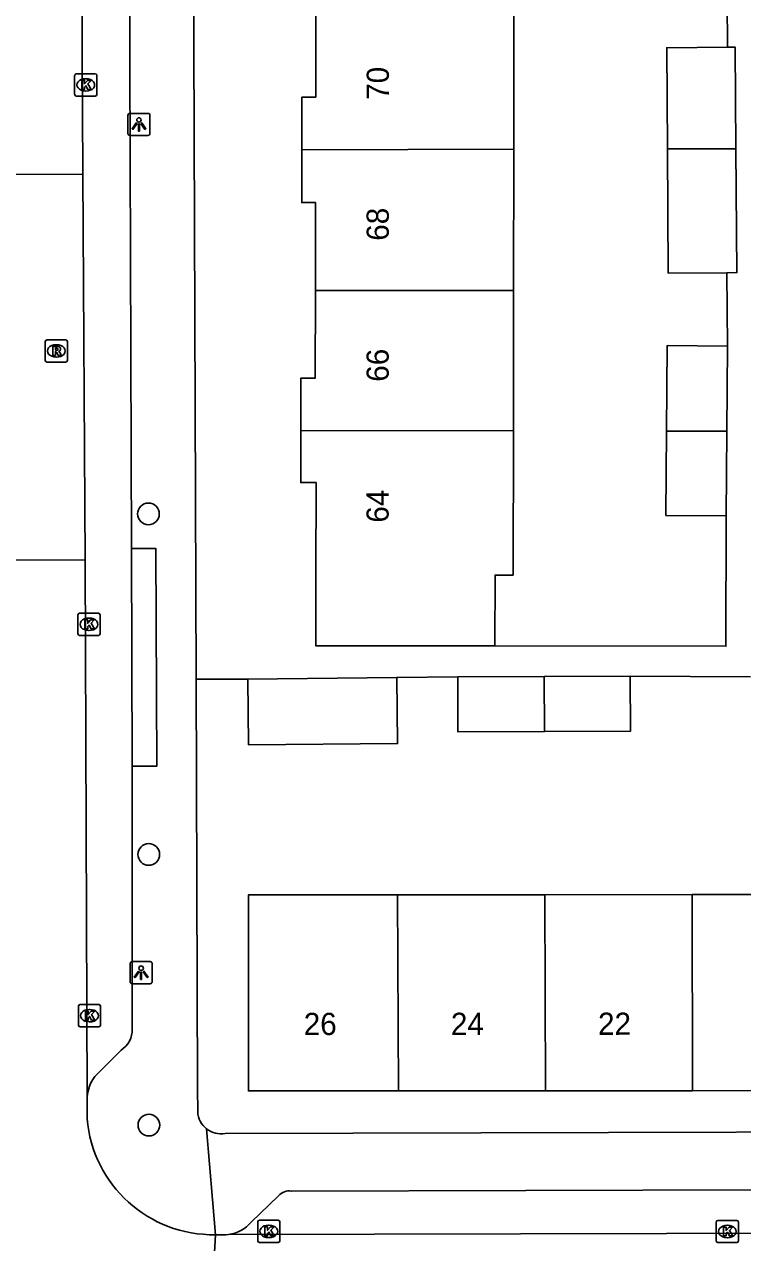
# Model space of a CAD drawing. Extents: x 160732 to 162105, y 387428 to 388479.
# Drawn here: x 161158.5 to 161190.9, y 388093.4 to 388148.3 of the extents above; entities that cross this region are included whole.
import ezdxf

# ---------------------------------------------------------------- set-up
doc = ezdxf.new("R2010")
doc.units = 0
for name, color, linetype in [('IMGEO_Boom', 7, 'Continuous'), ('IMGEO_Kolk', 7, 'Continuous'), ('IMGEO_Lichtpunt', 7, 'Continuous'), ('IMGEO_Pand', 7, 'Continuous'), ('IMGEO_Pand_nummerreeks', 7, 'Continuous'), ('IMGEO_Rijbaan_lokaal_open', 7, 'Continuous'), ('IMGEO_Rioolput', 7, 'Continuous'), ('IMGEO_Voetpad_open', 7, 'Continuous')]:
    doc.layers.add(name, color=color, linetype=linetype)

msp = doc.modelspace()

# ---------------------------------------------------------------- linework, layer by layer
at = {"layer": 'IMGEO_Boom'}
for centre in [(161164.081, 388126.239), (161164.092, 388110.889), (161164.1, 388098.689)]:
    msp.add_circle(centre, 0.489, dxfattribs=at)
at = {"layer": 'IMGEO_Kolk'}
for p, q in [((161160.752, 388145.149), (161160.752, 388146.001)), ((161160.827, 388146.075), (161161.679, 388146.075)), ((161161.24, 388145.855), (161161.265, 388145.855)), ((161161.753, 388146.001), (161161.753, 388145.149)), ((161161.263, 388145.295), (161161.238, 388145.295)), ((161161.679, 388145.075), (161160.827, 388145.075)), ((161160.897, 388120.836), (161160.897, 388121.688)), ((161160.972, 388121.762), (161161.824, 388121.762)), ((161161.385, 388121.542), (161161.41, 388121.542)), ((161161.898, 388121.688), (161161.898, 388120.836)), ((161161.408, 388120.982), (161161.383, 388120.982)), ((161161.824, 388120.762), (161160.972, 388120.762)), ((161160.92, 388103.195), (161160.92, 388104.047)), ((161160.995, 388104.121), (161161.847, 388104.121)), ((161161.921, 388104.047), (161161.921, 388103.195)), ((161161.408, 388103.901), (161161.433, 388103.901)), ((161161.847, 388103.121), (161160.995, 388103.121)), ((161161.431, 388103.341), (161161.406, 388103.341)), ((161169.007, 388093.473), (161169.007, 388094.325)), ((161169.082, 388094.399), (161169.934, 388094.399)), ((161169.495, 388094.179), (161169.52, 388094.179)), ((161170.008, 388094.325), (161170.008, 388093.473)), ((161189.689, 388093.467), (161189.689, 388094.319)), ((161189.764, 388094.393), (161190.616, 388094.393)), ((161190.177, 388094.173), (161190.202, 388094.173)), ((161190.69, 388094.319), (161190.69, 388093.467)), ((161169.518, 388093.619), (161169.493, 388093.619)), ((161190.2, 388093.613), (161190.175, 388093.613)), ((161169.934, 388093.399), (161169.082, 388093.399)), ((161190.616, 388093.393), (161189.764, 388093.393))]:
    msp.add_line(p, q, dxfattribs=at)
for points in [[(161160.752, 388145.149), (161160.752, 388146.001)], [(161160.827, 388146.075), (161161.679, 388146.075)], [(161161.073, 388145.775), (161161.196, 388145.775), (161161.196, 388145.624), (161161.326, 388145.775), (161161.49, 388145.775), (161161.344, 388145.624), (161161.497, 388145.375), (161161.345, 388145.375), (161161.26, 388145.539), (161161.196, 388145.472), (161161.196, 388145.375), (161161.073, 388145.375), (161161.073, 388145.775)], [(161161.753, 388146.001), (161161.753, 388145.149)], [(161161.679, 388145.075), (161160.827, 388145.075)], [(161160.897, 388120.836), (161160.897, 388121.688)], [(161160.972, 388121.762), (161161.824, 388121.762)], [(161161.898, 388121.688), (161161.898, 388120.836)], [(161161.218, 388121.462), (161161.341, 388121.462), (161161.341, 388121.311), (161161.471, 388121.462), (161161.635, 388121.462), (161161.489, 388121.311), (161161.642, 388121.062), (161161.49, 388121.062), (161161.405, 388121.226), (161161.341, 388121.159), (161161.341, 388121.062), (161161.218, 388121.062), (161161.218, 388121.462)], [(161161.824, 388120.762), (161160.972, 388120.762)], [(161160.92, 388103.195), (161160.92, 388104.047)], [(161160.995, 388104.121), (161161.847, 388104.121)], [(161161.921, 388104.047), (161161.921, 388103.195)], [(161161.241, 388103.821), (161161.364, 388103.821), (161161.364, 388103.67), (161161.494, 388103.821), (161161.658, 388103.821), (161161.512, 388103.67), (161161.665, 388103.421), (161161.513, 388103.421), (161161.428, 388103.585), (161161.364, 388103.518), (161161.364, 388103.421), (161161.241, 388103.421), (161161.241, 388103.821)], [(161161.847, 388103.121), (161160.995, 388103.121)], [(161169.007, 388093.473), (161169.007, 388094.325)], [(161169.082, 388094.399), (161169.934, 388094.399)], [(161169.328, 388094.099), (161169.451, 388094.099), (161169.451, 388093.948), (161169.581, 388094.099), (161169.745, 388094.099), (161169.599, 388093.948), (161169.752, 388093.699), (161169.6, 388093.699), (161169.515, 388093.863), (161169.451, 388093.796), (161169.451, 388093.699), (161169.328, 388093.699), (161169.328, 388094.099)], [(161170.008, 388094.325), (161170.008, 388093.473)], [(161189.689, 388093.467), (161189.689, 388094.319)], [(161189.764, 388094.393), (161190.616, 388094.393)], [(161190.01, 388094.093), (161190.133, 388094.093), (161190.133, 388093.942), (161190.263, 388094.093), (161190.427, 388094.093), (161190.281, 388093.942), (161190.434, 388093.693), (161190.282, 388093.693), (161190.197, 388093.857), (161190.133, 388093.79), (161190.133, 388093.693), (161190.01, 388093.693), (161190.01, 388094.093)], [(161190.69, 388094.319), (161190.69, 388093.467)], [(161169.934, 388093.399), (161169.082, 388093.399)], [(161190.616, 388093.393), (161189.764, 388093.393)]]:
    msp.add_lwpolyline(points, dxfattribs=at)
for centre, start, end in [((161160.829, 388145.999), 91.552, 178.448), ((161160.829, 388145.999), 91.552, 178.448), ((161161.677, 388145.999), 1.552, 88.448), ((161161.677, 388145.999), 1.552, 88.448), ((161160.829, 388145.151), 181.552, 268.448), ((161160.829, 388145.151), 181.552, 268.448), ((161161.677, 388145.151), 271.552, 358.448), ((161161.677, 388145.151), 271.552, 358.448), ((161160.974, 388121.686), 91.552, 178.448), ((161160.974, 388121.686), 91.552, 178.448), ((161161.822, 388121.686), 1.552, 88.448), ((161161.822, 388121.686), 1.552, 88.448), ((161160.974, 388120.838), 181.552, 268.448), ((161160.974, 388120.838), 181.552, 268.448), ((161161.822, 388120.838), 271.552, 358.448), ((161161.822, 388120.838), 271.552, 358.448), ((161160.997, 388104.045), 91.552, 178.448), ((161160.997, 388104.045), 91.552, 178.448), ((161161.845, 388104.045), 1.552, 88.448), ((161161.845, 388104.045), 1.552, 88.448), ((161160.997, 388103.197), 181.552, 268.448), ((161160.997, 388103.197), 181.552, 268.448), ((161161.845, 388103.197), 271.552, 358.448), ((161161.845, 388103.197), 271.552, 358.448), ((161169.084, 388094.323), 91.552, 178.448), ((161169.084, 388094.323), 91.552, 178.448), ((161169.932, 388094.323), 1.552, 88.448), ((161169.932, 388094.323), 1.552, 88.448), ((161189.766, 388094.317), 91.552, 178.448), ((161189.766, 388094.317), 91.552, 178.448), ((161190.614, 388094.317), 1.552, 88.448), ((161190.614, 388094.317), 1.552, 88.448), ((161169.084, 388093.475), 181.552, 268.448), ((161169.084, 388093.475), 181.552, 268.448), ((161169.932, 388093.475), 271.552, 358.448), ((161169.932, 388093.475), 271.552, 358.448), ((161189.766, 388093.469), 181.552, 268.448), ((161189.766, 388093.469), 181.552, 268.448), ((161190.614, 388093.469), 271.552, 358.448), ((161190.614, 388093.469), 271.552, 358.448)]:
    msp.add_arc(centre, 0.0765, start, end, dxfattribs=at)
for centre, major_axis, ratio, start_param, end_param in [((161161.239, 388145.575), (-0.387, 0.002), 0.722429, 4.712389, 7.853982), ((161161.264, 388145.575), (-0.39, 0.002), 0.717154, 1.570796, 4.712389), ((161161.384, 388121.262), (-0.387, 0.002), 0.722429, 4.712389, 7.853982), ((161161.409, 388121.262), (-0.39, 0.002), 0.717154, 1.570796, 4.712389), ((161161.407, 388103.621), (-0.387, 0.002), 0.722429, 4.712389, 7.853982), ((161161.432, 388103.621), (-0.39, 0.002), 0.717154, 1.570796, 4.712389), ((161169.494, 388093.899), (-0.387, 0.002), 0.722429, 4.712389, 7.853982), ((161169.519, 388093.899), (-0.39, 0.002), 0.717154, 1.570796, 4.712389), ((161190.176, 388093.893), (-0.387, 0.002), 0.722429, 4.712389, 7.853982), ((161190.201, 388093.893), (-0.39, 0.002), 0.717154, 1.570796, 4.712389)]:
    msp.add_ellipse(centre, major_axis=major_axis, ratio=ratio, start_param=start_param, end_param=end_param, dxfattribs=at)
at = {"layer": 'IMGEO_Lichtpunt'}
for p, q in [((161163.152, 388144.198), (161163.152, 388143.391)), ((161163.152, 388144.198), (161163.152, 388143.391)), ((161164.054, 388144.293), (161163.246, 388144.293)), ((161164.054, 388144.293), (161163.246, 388144.293)), ((161164.148, 388143.391), (161164.148, 388144.198)), ((161164.148, 388143.391), (161164.148, 388144.198)), ((161163.246, 388143.297), (161164.054, 388143.297)), ((161163.246, 388143.297), (161164.054, 388143.297)), ((161163.251, 388105.963), (161163.251, 388105.156)), ((161163.251, 388105.963), (161163.251, 388105.156)), ((161164.153, 388106.058), (161163.345, 388106.058)), ((161164.153, 388106.058), (161163.345, 388106.058)), ((161164.247, 388105.156), (161164.247, 388105.963)), ((161164.247, 388105.156), (161164.247, 388105.963)), ((161163.345, 388105.062), (161164.153, 388105.062)), ((161163.345, 388105.062), (161164.153, 388105.062))]:
    msp.add_line(p, q, dxfattribs=at)
for points in [[(161163.526, 388143.862), (161163.565, 388143.834), (161163.377, 388143.572), (161163.339, 388143.599), (161163.526, 388143.862)], [(161163.628, 388143.814), (161163.675, 388143.814), (161163.675, 388143.492), (161163.628, 388143.492), (161163.628, 388143.814)], [(161163.738, 388143.834), (161163.776, 388143.861), (161163.963, 388143.599), (161163.924, 388143.571), (161163.738, 388143.834)], [(161163.625, 388105.627), (161163.664, 388105.599), (161163.476, 388105.337), (161163.438, 388105.364), (161163.625, 388105.627)], [(161163.727, 388105.579), (161163.774, 388105.579), (161163.774, 388105.257), (161163.727, 388105.257), (161163.727, 388105.579)], [(161163.837, 388105.599), (161163.875, 388105.626), (161164.062, 388105.364), (161164.023, 388105.336), (161163.837, 388105.599)]]:
    msp.add_lwpolyline(points, dxfattribs=at)
for centre in [(161163.651, 388143.996), (161163.75, 388105.761)]:
    msp.add_circle(centre, 0.0994, dxfattribs=at)
for centre, start, end in [((161163.246, 388144.198), 90, 180), ((161163.246, 388144.198), 90, 180), ((161164.054, 388144.198), 0, 90), ((161164.054, 388144.198), 0, 90), ((161163.246, 388143.391), 180, 270), ((161163.246, 388143.391), 180, 270), ((161164.054, 388143.391), 270, 0), ((161164.054, 388143.391), 270, 360), ((161163.345, 388105.963), 90, 180), ((161163.345, 388105.963), 90, 180), ((161164.153, 388105.963), 0, 90), ((161164.153, 388105.963), 0, 90), ((161163.345, 388105.156), 180, 270), ((161163.345, 388105.156), 180, 270), ((161164.153, 388105.156), 270, 0), ((161164.153, 388105.156), 270, 360)]:
    msp.add_arc(centre, 0.0946, start, end, dxfattribs=at)
at = {"layer": 'IMGEO_Pand'}
for points in [[(161171, 388142.65), (161171.003, 388145.028), (161171.627, 388145.028), (161171.633, 388148.992)], [(161180.565, 388149.007), (161180.556, 388142.675)], [(161190.201, 388147.273), (161187.452, 388147.253), (161187.485, 388142.693)], [(161190.201, 388147.273), (161190.543, 388147.276), (161190.576, 388142.701)], [(161171, 388142.65), (161170.997, 388140.269), (161171.615, 388140.268), (161171.61, 388136.315)], [(161180.556, 388142.675), (161171, 388142.65)], [(161180.547, 388136.303), (161180.556, 388142.675)], [(161187.485, 388142.693), (161190.576, 388142.701)], [(161187.485, 388142.693), (161187.526, 388137.091), (161190.166, 388137.111)], [(161190.576, 388142.701), (161190.617, 388137.114), (161190.166, 388137.111)], [(161170.955, 388130.005), (161170.958, 388132.361), (161171.604, 388132.36), (161171.61, 388136.315)], [(161171.61, 388136.315), (161180.547, 388136.303)], [(161180.547, 388136.303), (161180.538, 388129.985)], [(161187.443, 388129.971), (161187.472, 388133.824), (161190.191, 388133.803)], [(161190.191, 388133.803), (161190.162, 388129.965)], [(161170.955, 388130.005), (161170.952, 388127.652), (161171.638, 388127.651), (161171.632, 388123.494), (161171.627, 388120.298), (161179.707, 388120.286)], [(161180.538, 388129.985), (161170.955, 388130.005)], [(161179.707, 388120.286), (161179.712, 388123.483), (161180.528, 388123.482), (161180.538, 388129.985)], [(161190.133, 388126.15), (161187.415, 388126.17), (161187.443, 388129.971)], [(161187.443, 388129.971), (161190.162, 388129.965)], [(161190.162, 388129.965), (161190.133, 388126.15)], [(161168.569, 388118.796), (161175.284, 388118.862)], [(161175.284, 388118.862), (161175.313, 388115.888), (161168.598, 388115.822), (161168.569, 388118.796)], [(161178.027, 388118.888), (161181.93, 388118.904)], [(161181.938, 388116.43), (161178.038, 388116.414), (161178.027, 388118.888)], [(161181.93, 388118.904), (161185.812, 388118.92)], [(161181.938, 388116.43), (161181.93, 388118.904)], [(161185.812, 388118.92), (161185.823, 388116.446), (161181.938, 388116.43)], [(161175.35, 388100.231), (161168.592, 388100.226), (161168.585, 388109.065), (161175.319, 388109.07)], [(161175.319, 388109.07), (161181.961, 388109.075)], [(161175.35, 388100.231), (161175.319, 388109.07)], [(161181.961, 388109.075), (161188.594, 388109.08)], [(161181.989, 388100.236), (161181.961, 388109.075)], [(161188.594, 388109.08), (161195.217, 388109.084)], [(161188.62, 388100.24), (161188.594, 388109.08)], [(161181.989, 388100.236), (161175.35, 388100.231)], [(161188.62, 388100.24), (161181.989, 388100.236)], [(161195.251, 388100.245), (161188.62, 388100.24)]]:
    msp.add_lwpolyline(points, dxfattribs=at)
at = {"layer": 'IMGEO_Rijbaan_lokaal_open'}
for points in [[(161161.118, 388141.556), (161160.945, 388175.907)], [(161156.023, 388141.534), (161161.118, 388141.556)], [(161161.231, 388124.147), (161161.118, 388141.556)], [(161161.231, 388124.147), (161156.115, 388124.167)], [(161161.317, 388099.948), (161161.231, 388124.147)], [(161161.317, 388099.948), (161161.311, 388098.979)], [(161166.812, 388088.76), (161167.102, 388093.748)], [(161167.689, 388093.754), (161167.577, 388093.743), (161167.102, 388093.748)], [(161246.71, 388093.94), (161167.689, 388093.754)]]:
    msp.add_lwpolyline(points, dxfattribs=at)
msp.add_arc((161167.006, 388099.462), 5.715, 184.8512, 270.9659, dxfattribs=at)
at = {"layer": 'IMGEO_Rioolput'}
for p, q in [((161159.424, 388133.158), (161159.424, 388134.01)), ((161159.499, 388134.084), (161160.351, 388134.084)), ((161159.912, 388133.864), (161159.937, 388133.864)), ((161160.425, 388134.01), (161160.425, 388133.158)), ((161160.351, 388133.084), (161159.499, 388133.084)), ((161159.935, 388133.304), (161159.91, 388133.304))]:
    msp.add_line(p, q, dxfattribs=at)
for points in [[(161159.424, 388133.158), (161159.424, 388134.01)], [(161159.499, 388134.084), (161160.351, 388134.084)], [(161160.013, 388133.782), (161159.761, 388133.784), (161159.761, 388133.384)], [(161159.939, 388133.703), (161159.885, 388133.703), (161159.885, 388133.622)], [(161159.885, 388133.622), (161159.937, 388133.622)], [(161160.425, 388134.01), (161160.425, 388133.158)], [(161160.351, 388133.084), (161159.499, 388133.084)], [(161159.761, 388133.384), (161159.885, 388133.384), (161159.885, 388133.546), (161159.896, 388133.546)], [(161159.943, 388133.517), (161160.014, 388133.384), (161160.154, 388133.384), (161160.089, 388133.51)]]:
    msp.add_lwpolyline(points, dxfattribs=at)
for centre, radius, start, end in [((161159.501, 388134.008), 0.0765, 91.552, 178.448), ((161159.501, 388134.008), 0.0765, 91.552, 178.448), ((161159.921, 388133.811), 0.19, 274.7715, 282.9687), ((161159.945, 388133.607), 0.0964, 77.0061, 93.1865), ((161159.959, 388133.664), 0.0378, 276.6634, 79.6772), ((161160.012, 388133.672), 0.109, 350.3612, 89.416), ((161160.01, 388133.672), 0.112, 277.5842, 350.9817), ((161159.994, 388133.457), 0.108, 29.5134, 73.7905), ((161160.349, 388134.008), 0.0765, 1.552, 88.448), ((161160.349, 388134.008), 0.0765, 1.552, 88.448), ((161159.501, 388133.16), 0.0765, 181.552, 268.448), ((161159.501, 388133.16), 0.0765, 181.552, 268.448), ((161159.895, 388133.493), 0.0533, 26.0293, 88.6989), ((161160.349, 388133.16), 0.0765, 271.552, 358.448), ((161160.349, 388133.16), 0.0765, 271.552, 358.448)]:
    msp.add_arc(centre, radius, start, end, dxfattribs=at)
for centre, major_axis, ratio, start_param, end_param in [((161159.911, 388133.584), (-0.387, 0.002), 0.722429, 4.712389, 7.853982), ((161159.936, 388133.584), (-0.39, 0.002), 0.717154, 1.570796, 4.712389)]:
    msp.add_ellipse(centre, major_axis=major_axis, ratio=ratio, start_param=start_param, end_param=end_param, dxfattribs=at)
at = {"layer": 'IMGEO_Voetpad_open'}
for points in [[(161163.148, 388172.958), (161163.314, 388124.684)], [(161166.228, 388118.787), (161166.047, 388167.875), (161165.999, 388172.465)], [(161190.17, 388151.5), (161190.201, 388147.273)], [(161190.166, 388137.111), (161190.191, 388133.803)], [(161190.133, 388126.15), (161190.124, 388120.271), (161179.707, 388120.286)], [(161163.347, 388114.872), (161163.314, 388124.684)], [(161163.314, 388124.684), (161164.407, 388124.684), (161164.46, 388114.872), (161163.347, 388114.872)], [(161168.569, 388118.796), (161166.228, 388118.787)], [(161166.3, 388099.289), (161166.296, 388100.338), (161166.228, 388118.787)], [(161178.027, 388118.888), (161175.284, 388118.862)], [(161191.226, 388118.897), (161185.812, 388118.92)], [(161163.347, 388114.872), (161163.349, 388103.016)], [(161162.844, 388102.071), (161161.902, 388101.117)], [(161167.102, 388093.748), (161166.702, 388098.521)], [(161167.543, 388098.312), (161213.654, 388098.423)], [(161170.524, 388095.717), (161212.798, 388095.827)], [(161168.709, 388094.317), (161169.952, 388095.503)]]:
    msp.add_lwpolyline(points, dxfattribs=at)
for centre, radius, start, end in [((161162.268, 388102.986), 1.081, 302.184, 1.5766), ((161162.956, 388099.859), 1.642, 129.9524, 176.8783), ((161167.359, 388099.354), 1.061, 183.5121, 231.7464), ((161167.354, 388099.348), 1.053, 231.7515, 280.3364), ((161170.434, 388095.085), 0.638, 81.9131, 139.1112), ((161167.481, 388095.337), 1.596, 277.492, 320.3019)]:
    msp.add_arc(centre, radius, start, end, dxfattribs=at)

# ---------------------------------------------------------------- texts
at = {"layer": 'IMGEO_Pand_nummerreeks'}
for s, rotation, p in [('70', 89.9729, (161174.922, 388144.903)), ('68', 89.9729, (161174.919, 388138.551)), ('66', 89.9729, (161174.916, 388132.195)), ('64', 89.9729, (161174.913, 388125.843)), ('26', 0.0388, (161171.083, 388102.748)), ('24', 0.0388, (161177.721, 388102.753)), ('22', 0.0388, (161184.356, 388102.757))]:
    msp.add_text(s, height=1, rotation=rotation, dxfattribs=at).set_placement(p)

doc.saveas('drawing.dxf')
